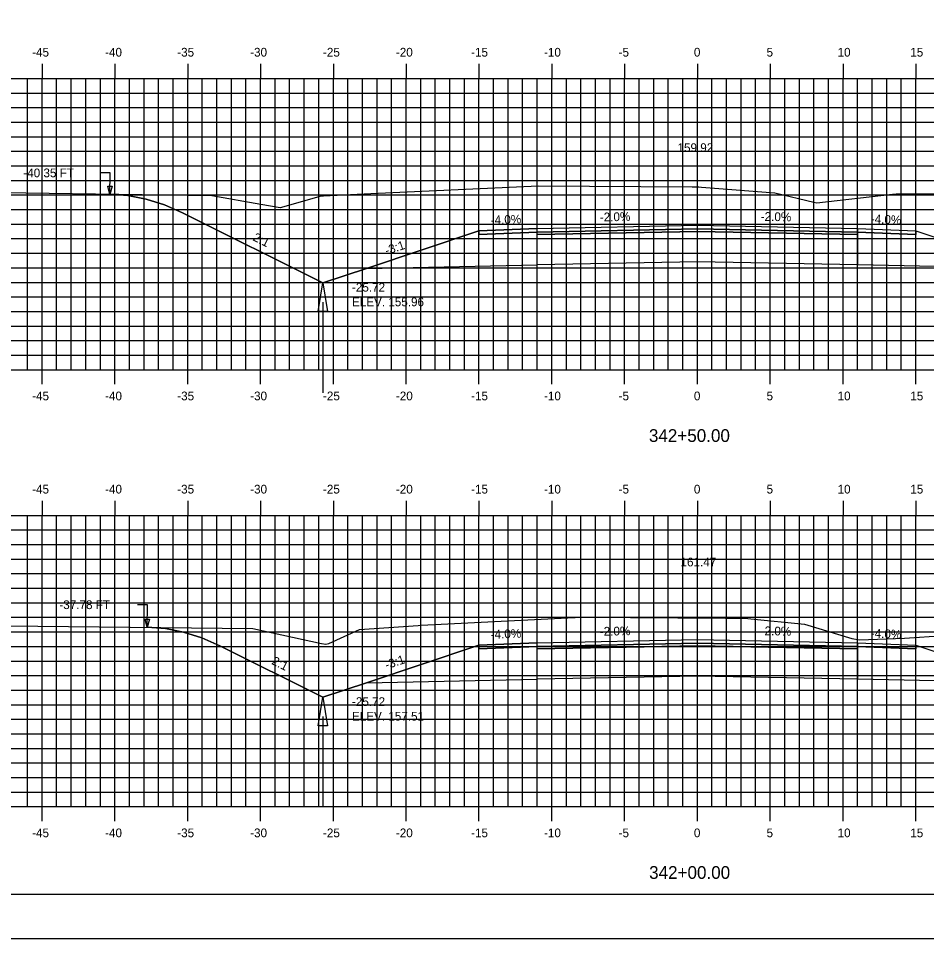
# Model space of a CAD drawing. Extents: x 1143198 to 1143368, y 608981 to 609091.
# Drawn here: x 1143234.7 to 1143297.1, y 608981.3 to 609044.5 of the extents above; entities that cross this region are included whole.
import ezdxf

# ---------------------------------------------------------------- set-up
doc = ezdxf.new("R2010")
doc.units = 0
for name, color, linetype in [('ANNOTATION', 7, 'Continuous'), ('BORDER', 7, 'Continuous'), ('D_Drainage_Ditch_Line', 7, 'Continuous'), ('D_Roadway_Centerline', 7, 'Continuous'), ('D_Roadway_Centerline_Text', 7, 'Continuous'), ('D_Roadway_Edge_Shoulder', 7, 'Continuous'), ('D_Roadway_Edge_TW', 7, 'Continuous'), ('D_Roadway_Pavement', 7, 'Continuous'), ('D_Roadway_SlopeLines', 7, 'Continuous'), ('D_Roadway_SubGrade', 7, 'Continuous'), ('D_Text_Standard', 7, 'Continuous'), ('H_V ANNOTATION', 7, 'Continuous'), ('MAJOR', 7, 'Continuous'), ('MINOR', 7, 'Continuous'), ('PLOT BOUNDARY', 7, 'Continuous'), ('S_Roadway_Centerline', 7, 'Continuous')]:
    doc.layers.add(name, color=color, linetype=linetype)

msp = doc.modelspace()

# ---------------------------------------------------------------- linework, layer by layer
for points in [[(1143240.971, 609032.398), (1143242.221, 609032.303), (1143243.471, 609032.057), (1143244.721, 609031.659), (1143245.971, 609031.11), (1143255.598, 609026.296), (1143258.598, 609027.296), (1143266.322, 609029.871), (1143266.323, 609029.871), (1143270.323, 609030.031), (1143281.323, 609030.251), (1143292.323, 609030.031), (1143296.323, 609029.871), (1143304.047, 609027.296), (1143307.047, 609026.296), (1143317.091, 609031.319), (1143318.341, 609031.867), (1143319.591, 609032.26), (1143320.841, 609032.5), (1143322.091, 609032.585)], [(1143243.539, 609002.652), (1143244.789, 609002.562), (1143246.039, 609002.32), (1143247.289, 609001.925), (1143248.539, 609001.376), (1143255.598, 608997.847), (1143258.598, 608998.847), (1143266.322, 609001.421), (1143266.323, 609001.421), (1143270.323, 609001.581), (1143281.323, 609001.801), (1143292.323, 609001.581), (1143296.323, 609001.421), (1143304.047, 608998.847), (1143307.047, 608997.847), (1143312.886, 609000.767), (1143314.136, 609001.313), (1143315.386, 609001.7), (1143316.636, 609001.93), (1143317.886, 609002.001)]]:
    msp.add_lwpolyline(points)
at = {"layer": 'BORDER'}
msp.add_lwpolyline([(1143206.323, 608984.335), (1143366.323, 608984.335), (1143366.323, 609089.335), (1143206.323, 609089.335)], close=True, dxfattribs=at)
at = {"layer": 'D_Drainage_Ditch_Line'}
for p, q in [((1143255.599, 609024.984), (1143255.598, 609018.741)), ((1143255.599, 608996.534), (1143255.598, 608990.291))]:
    msp.add_line(p, q, dxfattribs=at)
for points in [[(1143255.927, 609024.328), (1143255.27, 609024.328), (1143255.598, 609026.296)], [(1143255.927, 608995.878), (1143255.27, 608995.878), (1143255.598, 608997.847)]]:
    msp.add_lwpolyline(points, close=True, dxfattribs=at)
at = {"layer": 'D_Roadway_Edge_Shoulder'}
for points in [[(1143270.323, 609030.031), (1143266.323, 609029.871), (1143266.323, 609029.621), (1143270.323, 609029.781)], [(1143292.323, 609030.031), (1143296.323, 609029.871), (1143296.323, 609029.621), (1143292.323, 609029.781)], [(1143270.323, 609001.581), (1143266.323, 609001.421), (1143266.323, 609001.171), (1143270.323, 609001.331)], [(1143292.323, 609001.581), (1143296.323, 609001.421), (1143296.323, 609001.171), (1143292.323, 609001.331)]]:
    msp.add_lwpolyline(points, close=True, dxfattribs=at)
at = {"layer": 'D_Roadway_Edge_TW'}
for points in [[(1143270.323, 609029.781), (1143270.323, 609030.031), (1143281.323, 609030.251), (1143292.323, 609030.031), (1143292.323, 609029.781), (1143281.323, 609030.001)], [(1143270.323, 609001.331), (1143270.323, 609001.581), (1143281.323, 609001.801), (1143292.323, 609001.581), (1143292.323, 609001.331), (1143281.323, 609001.551)]]:
    msp.add_lwpolyline(points, close=True, dxfattribs=at)
at = {"layer": 'D_Roadway_Pavement'}
for points in [[(1143270.323, 609029.614), (1143270.323, 609029.781), (1143281.323, 609030.001), (1143292.323, 609029.781), (1143292.323, 609029.614), (1143281.323, 609029.834)], [(1143270.323, 609001.165), (1143270.323, 609001.331), (1143281.323, 609001.551), (1143292.323, 609001.331), (1143292.323, 609001.165), (1143281.323, 609001.385)]]:
    msp.add_lwpolyline(points, close=True, dxfattribs=at)
at = {"layer": 'D_Roadway_SlopeLines'}
for points in [[(1143255.598, 609026.296), (1143245.971, 609031.11), (1143244.721, 609031.659), (1143243.471, 609032.057), (1143242.221, 609032.303), (1143240.971, 609032.398)], [(1143258.598, 609027.296), (1143255.598, 609026.296)], [(1143255.598, 608997.847), (1143248.539, 609001.376), (1143247.289, 609001.925), (1143246.039, 609002.32), (1143244.789, 609002.562), (1143243.539, 609002.652)], [(1143258.598, 608998.847), (1143255.598, 608997.847)]]:
    msp.add_lwpolyline(points, dxfattribs=at)
at = {"layer": 'D_Roadway_SubGrade'}
for points in [[(1143270.323, 609029.614), (1143270.323, 609029.781), (1143266.323, 609029.621), (1143266.323, 609029.871), (1143266.322, 609029.871), (1143258.598, 609027.296), (1143270.323, 609027.531)], [(1143270.323, 609027.531), (1143270.323, 609029.614), (1143281.323, 609029.834), (1143292.323, 609029.614), (1143292.323, 609027.531), (1143281.323, 609027.751)], [(1143292.323, 609029.614), (1143292.323, 609029.781), (1143296.323, 609029.621), (1143296.323, 609029.871), (1143296.323, 609029.871), (1143304.047, 609027.296), (1143292.323, 609027.531)], [(1143270.323, 609001.165), (1143270.323, 609001.331), (1143266.323, 609001.171), (1143266.323, 609001.421), (1143266.322, 609001.421), (1143258.598, 608998.847), (1143270.323, 608999.081)], [(1143270.323, 608999.081), (1143270.323, 609001.165), (1143281.323, 609001.385), (1143292.323, 609001.165), (1143292.323, 608999.081), (1143281.323, 608999.301)], [(1143292.323, 609001.165), (1143292.323, 609001.331), (1143296.323, 609001.171), (1143296.323, 609001.421), (1143296.323, 609001.421), (1143304.047, 608998.847), (1143292.323, 608999.081)]]:
    msp.add_lwpolyline(points, close=True, dxfattribs=at)
at = {"layer": 'D_Text_Standard'}
for points in [[(1143240.971, 609032.36), (1143241.007, 609033.85), (1143240.327, 609033.85)], [(1143243.539, 609002.626), (1143243.558, 609004.201), (1143242.878, 609004.201)]]:
    msp.add_lwpolyline(points, dxfattribs=at)
for points in [[(1143240.971, 609032.36), (1143240.839, 609032.946), (1143241.13, 609032.939)], [(1143243.539, 609002.626), (1143243.401, 609003.21), (1143243.692, 609003.207)]]:
    msp.add_lwpolyline(points, close=True, dxfattribs=at)
at = {"layer": 'MAJOR'}
for p, q in [((1143236.323, 609041.337), (1143236.323, 609040.335)), ((1143241.323, 609041.337), (1143241.323, 609040.335)), ((1143246.323, 609041.337), (1143246.323, 609040.335)), ((1143251.323, 609041.337), (1143251.323, 609040.335)), ((1143256.323, 609041.337), (1143256.323, 609040.335)), ((1143261.323, 609041.337), (1143261.323, 609040.335)), ((1143266.323, 609041.337), (1143266.323, 609040.335)), ((1143271.323, 609041.337), (1143271.323, 609040.335)), ((1143276.323, 609041.337), (1143276.323, 609040.335)), ((1143281.323, 609041.337), (1143281.323, 609040.335)), ((1143286.323, 609041.337), (1143286.323, 609040.335)), ((1143291.323, 609041.337), (1143291.323, 609040.335)), ((1143296.323, 609041.337), (1143296.323, 609040.335)), ((1143211.323, 609040.335), (1143351.323, 609040.335)), ((1143211.323, 609040.335), (1143351.323, 609040.335)), ((1143236.323, 609020.335), (1143236.323, 609040.335)), ((1143241.323, 609020.335), (1143241.323, 609040.335)), ((1143246.323, 609020.335), (1143246.323, 609040.335)), ((1143251.323, 609020.335), (1143251.323, 609040.335)), ((1143256.323, 609020.335), (1143256.323, 609040.335)), ((1143261.323, 609020.335), (1143261.323, 609040.335)), ((1143266.323, 609020.335), (1143266.323, 609040.335)), ((1143271.323, 609020.335), (1143271.323, 609040.335)), ((1143276.323, 609020.335), (1143276.323, 609040.335)), ((1143281.323, 609020.335), (1143281.323, 609040.335)), ((1143286.323, 609020.335), (1143286.323, 609040.335)), ((1143291.323, 609020.335), (1143291.323, 609040.335)), ((1143296.323, 609020.335), (1143296.323, 609040.335)), ((1143211.323, 609035.335), (1143351.323, 609035.335)), ((1143211.323, 609030.335), (1143351.323, 609030.335)), ((1143211.323, 609025.335), (1143351.323, 609025.335)), ((1143211.323, 609020.335), (1143351.323, 609020.335)), ((1143211.323, 609020.335), (1143351.323, 609020.335)), ((1143236.323, 609019.333), (1143236.323, 609020.335)), ((1143241.323, 609019.333), (1143241.323, 609020.335)), ((1143246.323, 609019.333), (1143246.323, 609020.335)), ((1143251.323, 609019.333), (1143251.323, 609020.335)), ((1143256.323, 609019.333), (1143256.323, 609020.335)), ((1143261.323, 609019.333), (1143261.323, 609020.335)), ((1143266.323, 609019.333), (1143266.323, 609020.335)), ((1143271.323, 609019.333), (1143271.323, 609020.335)), ((1143276.323, 609019.333), (1143276.323, 609020.335)), ((1143281.323, 609019.333), (1143281.323, 609020.335)), ((1143286.323, 609019.333), (1143286.323, 609020.335)), ((1143291.323, 609019.333), (1143291.323, 609020.335)), ((1143296.323, 609019.333), (1143296.323, 609020.335)), ((1143236.323, 609011.337), (1143236.323, 609010.335)), ((1143241.323, 609011.337), (1143241.323, 609010.335)), ((1143246.323, 609011.337), (1143246.323, 609010.335)), ((1143251.323, 609011.337), (1143251.323, 609010.335)), ((1143256.323, 609011.337), (1143256.323, 609010.335)), ((1143261.323, 609011.337), (1143261.323, 609010.335)), ((1143266.323, 609011.337), (1143266.323, 609010.335)), ((1143271.323, 609011.337), (1143271.323, 609010.335)), ((1143276.323, 609011.337), (1143276.323, 609010.335)), ((1143281.323, 609011.337), (1143281.323, 609010.335)), ((1143286.323, 609011.337), (1143286.323, 609010.335)), ((1143291.323, 609011.337), (1143291.323, 609010.335)), ((1143296.323, 609011.337), (1143296.323, 609010.335)), ((1143211.323, 609010.335), (1143351.323, 609010.335)), ((1143211.323, 609010.335), (1143351.323, 609010.335)), ((1143236.323, 608990.335), (1143236.323, 609010.335)), ((1143241.323, 608990.335), (1143241.323, 609010.335)), ((1143246.323, 608990.335), (1143246.323, 609010.335)), ((1143251.323, 608990.335), (1143251.323, 609010.335)), ((1143256.323, 608990.335), (1143256.323, 609010.335)), ((1143261.323, 608990.335), (1143261.323, 609010.335)), ((1143266.323, 608990.335), (1143266.323, 609010.335)), ((1143271.323, 608990.335), (1143271.323, 609010.335)), ((1143276.323, 608990.335), (1143276.323, 609010.335)), ((1143281.323, 608990.335), (1143281.323, 609010.335)), ((1143286.323, 608990.335), (1143286.323, 609010.335)), ((1143291.323, 608990.335), (1143291.323, 609010.335)), ((1143296.323, 608990.335), (1143296.323, 609010.335)), ((1143211.323, 609005.335), (1143351.323, 609005.335)), ((1143211.323, 609000.335), (1143351.323, 609000.335)), ((1143211.323, 608995.335), (1143351.323, 608995.335)), ((1143211.323, 608990.335), (1143351.323, 608990.335)), ((1143211.323, 608990.335), (1143351.323, 608990.335)), ((1143236.323, 608989.333), (1143236.323, 608990.335)), ((1143241.323, 608989.333), (1143241.323, 608990.335)), ((1143246.323, 608989.333), (1143246.323, 608990.335)), ((1143251.323, 608989.333), (1143251.323, 608990.335)), ((1143256.323, 608989.333), (1143256.323, 608990.335)), ((1143261.323, 608989.333), (1143261.323, 608990.335)), ((1143266.323, 608989.333), (1143266.323, 608990.335)), ((1143271.323, 608989.333), (1143271.323, 608990.335)), ((1143276.323, 608989.333), (1143276.323, 608990.335)), ((1143281.323, 608989.333), (1143281.323, 608990.335)), ((1143286.323, 608989.333), (1143286.323, 608990.335)), ((1143291.323, 608989.333), (1143291.323, 608990.335)), ((1143296.323, 608989.333), (1143296.323, 608990.335))]:
    msp.add_line(p, q, dxfattribs=at)
at = {"layer": 'MINOR'}
for p, q in [((1143235.323, 609020.335), (1143235.323, 609040.335)), ((1143237.323, 609020.335), (1143237.323, 609040.335)), ((1143238.323, 609020.335), (1143238.323, 609040.335)), ((1143239.323, 609020.335), (1143239.323, 609040.335)), ((1143240.323, 609020.335), (1143240.323, 609040.335)), ((1143242.323, 609020.335), (1143242.323, 609040.335)), ((1143243.323, 609020.335), (1143243.323, 609040.335)), ((1143244.323, 609020.335), (1143244.323, 609040.335)), ((1143245.323, 609020.335), (1143245.323, 609040.335)), ((1143247.323, 609020.335), (1143247.323, 609040.335)), ((1143248.323, 609020.335), (1143248.323, 609040.335)), ((1143249.323, 609020.335), (1143249.323, 609040.335)), ((1143250.323, 609020.335), (1143250.323, 609040.335)), ((1143252.323, 609020.335), (1143252.323, 609040.335)), ((1143253.323, 609020.335), (1143253.323, 609040.335)), ((1143254.323, 609020.335), (1143254.323, 609040.335)), ((1143255.323, 609020.335), (1143255.323, 609040.335)), ((1143257.323, 609020.335), (1143257.323, 609040.335)), ((1143258.323, 609020.335), (1143258.323, 609040.335)), ((1143259.323, 609020.335), (1143259.323, 609040.335)), ((1143260.323, 609020.335), (1143260.323, 609040.335)), ((1143262.323, 609020.335), (1143262.323, 609040.335)), ((1143263.323, 609020.335), (1143263.323, 609040.335)), ((1143264.323, 609020.335), (1143264.323, 609040.335)), ((1143265.323, 609020.335), (1143265.323, 609040.335)), ((1143267.323, 609020.335), (1143267.323, 609040.335)), ((1143268.323, 609020.335), (1143268.323, 609040.335)), ((1143269.323, 609020.335), (1143269.323, 609040.335)), ((1143270.323, 609020.335), (1143270.323, 609040.335)), ((1143272.323, 609020.335), (1143272.323, 609040.335)), ((1143273.323, 609020.335), (1143273.323, 609040.335)), ((1143274.323, 609020.335), (1143274.323, 609040.335)), ((1143275.323, 609020.335), (1143275.323, 609040.335)), ((1143277.323, 609020.335), (1143277.323, 609040.335)), ((1143278.323, 609020.335), (1143278.323, 609040.335)), ((1143279.323, 609020.335), (1143279.323, 609040.335)), ((1143280.323, 609020.335), (1143280.323, 609040.335)), ((1143282.323, 609020.335), (1143282.323, 609040.335)), ((1143283.323, 609020.335), (1143283.323, 609040.335)), ((1143284.323, 609020.335), (1143284.323, 609040.335)), ((1143285.323, 609020.335), (1143285.323, 609040.335)), ((1143287.323, 609020.335), (1143287.323, 609040.335)), ((1143288.323, 609020.335), (1143288.323, 609040.335)), ((1143289.323, 609020.335), (1143289.323, 609040.335)), ((1143290.323, 609020.335), (1143290.323, 609040.335)), ((1143292.323, 609020.335), (1143292.323, 609040.335)), ((1143293.323, 609020.335), (1143293.323, 609040.335)), ((1143294.323, 609020.335), (1143294.323, 609040.335)), ((1143295.323, 609020.335), (1143295.323, 609040.335)), ((1143211.323, 609039.335), (1143351.323, 609039.335)), ((1143211.323, 609038.335), (1143351.323, 609038.335)), ((1143211.323, 609037.335), (1143351.323, 609037.335)), ((1143211.323, 609036.335), (1143351.323, 609036.335)), ((1143211.323, 609034.335), (1143351.323, 609034.335)), ((1143211.323, 609033.335), (1143351.323, 609033.335)), ((1143211.323, 609032.335), (1143351.323, 609032.335)), ((1143211.323, 609031.335), (1143351.323, 609031.335)), ((1143211.323, 609029.335), (1143351.323, 609029.335)), ((1143211.323, 609028.335), (1143351.323, 609028.335)), ((1143211.323, 609027.335), (1143351.323, 609027.335)), ((1143211.323, 609026.335), (1143351.323, 609026.335)), ((1143211.323, 609024.335), (1143351.323, 609024.335)), ((1143211.323, 609023.335), (1143351.323, 609023.335)), ((1143211.323, 609022.335), (1143351.323, 609022.335)), ((1143211.323, 609021.335), (1143351.323, 609021.335)), ((1143235.323, 608990.335), (1143235.323, 609010.335)), ((1143237.323, 608990.335), (1143237.323, 609010.335)), ((1143238.323, 608990.335), (1143238.323, 609010.335)), ((1143239.323, 608990.335), (1143239.323, 609010.335)), ((1143240.323, 608990.335), (1143240.323, 609010.335)), ((1143242.323, 608990.335), (1143242.323, 609010.335)), ((1143243.323, 608990.335), (1143243.323, 609010.335)), ((1143244.323, 608990.335), (1143244.323, 609010.335)), ((1143245.323, 608990.335), (1143245.323, 609010.335)), ((1143247.323, 608990.335), (1143247.323, 609010.335)), ((1143248.323, 608990.335), (1143248.323, 609010.335)), ((1143249.323, 608990.335), (1143249.323, 609010.335)), ((1143250.323, 608990.335), (1143250.323, 609010.335)), ((1143252.323, 608990.335), (1143252.323, 609010.335)), ((1143253.323, 608990.335), (1143253.323, 609010.335)), ((1143254.323, 608990.335), (1143254.323, 609010.335)), ((1143255.323, 608990.335), (1143255.323, 609010.335)), ((1143257.323, 608990.335), (1143257.323, 609010.335)), ((1143258.323, 608990.335), (1143258.323, 609010.335)), ((1143259.323, 608990.335), (1143259.323, 609010.335)), ((1143260.323, 608990.335), (1143260.323, 609010.335)), ((1143262.323, 608990.335), (1143262.323, 609010.335)), ((1143263.323, 608990.335), (1143263.323, 609010.335)), ((1143264.323, 608990.335), (1143264.323, 609010.335)), ((1143265.323, 608990.335), (1143265.323, 609010.335)), ((1143267.323, 608990.335), (1143267.323, 609010.335)), ((1143268.323, 608990.335), (1143268.323, 609010.335)), ((1143269.323, 608990.335), (1143269.323, 609010.335)), ((1143270.323, 608990.335), (1143270.323, 609010.335)), ((1143272.323, 608990.335), (1143272.323, 609010.335)), ((1143273.323, 608990.335), (1143273.323, 609010.335)), ((1143274.323, 608990.335), (1143274.323, 609010.335)), ((1143275.323, 608990.335), (1143275.323, 609010.335)), ((1143277.323, 608990.335), (1143277.323, 609010.335)), ((1143278.323, 608990.335), (1143278.323, 609010.335)), ((1143279.323, 608990.335), (1143279.323, 609010.335)), ((1143280.323, 608990.335), (1143280.323, 609010.335)), ((1143282.323, 608990.335), (1143282.323, 609010.335)), ((1143283.323, 608990.335), (1143283.323, 609010.335)), ((1143284.323, 608990.335), (1143284.323, 609010.335)), ((1143285.323, 608990.335), (1143285.323, 609010.335)), ((1143287.323, 608990.335), (1143287.323, 609010.335)), ((1143288.323, 608990.335), (1143288.323, 609010.335)), ((1143289.323, 608990.335), (1143289.323, 609010.335)), ((1143290.323, 608990.335), (1143290.323, 609010.335)), ((1143292.323, 608990.335), (1143292.323, 609010.335)), ((1143293.323, 608990.335), (1143293.323, 609010.335)), ((1143294.323, 608990.335), (1143294.323, 609010.335)), ((1143295.323, 608990.335), (1143295.323, 609010.335)), ((1143211.323, 609009.335), (1143351.323, 609009.335)), ((1143211.323, 609008.335), (1143351.323, 609008.335)), ((1143211.323, 609007.335), (1143351.323, 609007.335)), ((1143211.323, 609006.335), (1143351.323, 609006.335)), ((1143211.323, 609004.335), (1143351.323, 609004.335)), ((1143211.323, 609003.335), (1143351.323, 609003.335)), ((1143211.323, 609002.335), (1143351.323, 609002.335)), ((1143211.323, 609001.335), (1143351.323, 609001.335)), ((1143211.323, 608999.335), (1143351.323, 608999.335)), ((1143211.323, 608998.335), (1143351.323, 608998.335)), ((1143211.323, 608997.335), (1143351.323, 608997.335)), ((1143211.323, 608996.335), (1143351.323, 608996.335)), ((1143211.323, 608994.335), (1143351.323, 608994.335)), ((1143211.323, 608993.335), (1143351.323, 608993.335)), ((1143211.323, 608992.335), (1143351.323, 608992.335)), ((1143211.323, 608991.335), (1143351.323, 608991.335))]:
    msp.add_line(p, q, dxfattribs=at)
at = {"layer": 'PLOT BOUNDARY'}
msp.add_lwpolyline([(1143198.23, 608981.276), (1143368.23, 608981.276), (1143368.23, 609091.276), (1143198.23, 609091.276)], close=True, dxfattribs=at)
at = {"layer": 'S_Roadway_Centerline'}
for points in [[(1143211.323, 609032.36), (1143212.821, 609032.367), (1143227.649, 609032.583), (1143228.657, 609032.591), (1143228.8, 609032.583), (1143247.983, 609032.292), (1143251.333, 609031.712), (1143252.666, 609031.463), (1143252.702, 609031.479), (1143255.498, 609032.264), (1143255.639, 609032.274), (1143258.901, 609032.437), (1143269.916, 609032.935), (1143270.397, 609032.96), (1143280.959, 609032.894), (1143281.429, 609032.891), (1143281.615, 609032.872), (1143286.632, 609032.483), (1143289.312, 609031.85), (1143289.514, 609031.79), (1143294.73, 609032.394), (1143294.969, 609032.411), (1143322.054, 609032.585)], [(1143211.323, 609002.363), (1143225.121, 609002.802), (1143229.877, 609002.851), (1143231.792, 609002.771), (1143250.788, 609002.578), (1143255.519, 609001.533), (1143255.814, 609001.5), (1143256.006, 609001.549), (1143258.121, 609002.489), (1143262.156, 609002.773), (1143262.353, 609002.794), (1143272.425, 609003.307), (1143273.453, 609003.347), (1143283.253, 609003.281), (1143284.582, 609003.27), (1143284.986, 609003.233), (1143288.677, 609002.857), (1143291.938, 609001.891), (1143292.456, 609001.78), (1143295.537, 609001.911), (1143298.268, 609002.095)]]:
    msp.add_lwpolyline(points, dxfattribs=at)

# ---------------------------------------------------------------- texts
at = {"layer": 'ANNOTATION'}
for s, rotation, p in [('-4.0%', 2.29061, (1143267.139, 609030.304)), ('-2.0%', 1.14576, (1143274.626, 609030.517)), ('-2.0%', 358.85424, (1143285.666, 609030.564)), ('-4.0%', 357.70939, (1143293.219, 609030.396)), ('2:1', 333.43495, (1143250.752, 609029.238)), ('-3:1', 18.43482, (1143259.977, 609028.21)), ('-4.0%', 2.29061, (1143267.139, 609001.855)), ('-2.0%', 1.14576, (1143274.626, 609002.068)), ('-2.0%', 358.85424, (1143285.666, 609002.115)), ('-4.0%', 357.70939, (1143293.219, 609001.946)), ('2:1', 333.43495, (1143252.036, 609000.146)), ('-3:1', 18.43482, (1143259.977, 608999.76))]:
    msp.add_text(s, height=0.6, rotation=rotation, dxfattribs=at).set_placement(p)
at = {"layer": 'D_Roadway_Centerline'}
for s, p in [('C', (1143281.318, 609030.251)), ('L', (1143281.323, 609030.244)), ('C', (1143281.318, 609001.801)), ('L', (1143281.323, 609001.794))]:
    msp.add_text(s, height=0.0146, dxfattribs=at).set_placement(p)
at = {"layer": 'D_Roadway_Centerline_Text'}
for s, p in [('159.92', (1143279.956, 609035.283)), ('161.47', (1143280.162, 609006.833))]:
    msp.add_text(s, height=0.6, dxfattribs=at).set_placement(p)
at = {"layer": 'D_Text_Standard'}
for s, p in [('-40.35 FT', (1143235.033, 609033.55)), ('-25.72', (1143257.599, 609025.696)), ('ELEV. 155.96', (1143257.599, 609024.694)), ('-37.78 FT', (1143237.509, 609003.901)), ('-25.72', (1143257.599, 608997.247)), ('ELEV. 157.51', (1143257.599, 608996.245))]:
    msp.add_text(s, height=0.6, dxfattribs=at).set_placement(p)
at = {"layer": 'H_V ANNOTATION'}
for s, height, p in [('-45', 0.6, (1143235.641, 609041.835)), ('-40', 0.6, (1143240.649, 609041.835)), ('-35', 0.6, (1143245.603, 609041.835)), ('-30', 0.6, (1143250.611, 609041.835)), ('-25', 0.6, (1143255.609, 609041.835)), ('-20', 0.6, (1143260.617, 609041.835)), ('-15', 0.6, (1143265.78, 609041.835)), ('-10', 0.6, (1143270.788, 609041.835)), ('-5', 0.6, (1143275.914, 609041.835)), ('0', 0.6, (1143281.082, 609041.835)), ('5', 0.6, (1143286.074, 609041.835)), ('10', 0.6, (1143290.948, 609041.835)), ('15', 0.6, (1143295.94, 609041.835)), ('-45', 0.6, (1143235.641, 609018.235)), ('-40', 0.6, (1143240.649, 609018.235)), ('-35', 0.6, (1143245.603, 609018.235)), ('-30', 0.6, (1143250.611, 609018.235)), ('-25', 0.6, (1143255.609, 609018.235)), ('-20', 0.6, (1143260.617, 609018.235)), ('-15', 0.6, (1143265.78, 609018.235)), ('-10', 0.6, (1143270.788, 609018.235)), ('-5', 0.6, (1143275.914, 609018.235)), ('0', 0.6, (1143281.082, 609018.235)), ('5', 0.6, (1143286.074, 609018.235)), ('10', 0.6, (1143290.948, 609018.235)), ('15', 0.6, (1143295.94, 609018.235)), ('342+50.00', 0.875, (1143277.991, 609015.378)), ('-45', 0.6, (1143235.641, 609011.835)), ('-40', 0.6, (1143240.649, 609011.835)), ('-35', 0.6, (1143245.603, 609011.835)), ('-30', 0.6, (1143250.611, 609011.835)), ('-25', 0.6, (1143255.609, 609011.835)), ('-20', 0.6, (1143260.617, 609011.835)), ('-15', 0.6, (1143265.78, 609011.835)), ('-10', 0.6, (1143270.788, 609011.835)), ('-5', 0.6, (1143275.914, 609011.835)), ('0', 0.6, (1143281.082, 609011.835)), ('5', 0.6, (1143286.074, 609011.835)), ('10', 0.6, (1143290.948, 609011.835)), ('15', 0.6, (1143295.94, 609011.835)), ('-45', 0.6, (1143235.641, 608988.235)), ('-40', 0.6, (1143240.649, 608988.235)), ('-35', 0.6, (1143245.603, 608988.235)), ('-30', 0.6, (1143250.611, 608988.235)), ('-25', 0.6, (1143255.609, 608988.235)), ('-20', 0.6, (1143260.617, 608988.235)), ('-15', 0.6, (1143265.78, 608988.235)), ('-10', 0.6, (1143270.788, 608988.235)), ('-5', 0.6, (1143275.914, 608988.235)), ('0', 0.6, (1143281.082, 608988.235)), ('5', 0.6, (1143286.074, 608988.235)), ('10', 0.6, (1143290.948, 608988.235)), ('15', 0.6, (1143295.94, 608988.235)), ('342+00.00', 0.875, (1143278.007, 608985.378))]:
    msp.add_text(s, height=height, dxfattribs=at).set_placement(p)
at = {"layer": 'S_Roadway_Centerline'}
for s, p in [('L', (1143270.389, 609032.952)), ('C', (1143270.392, 609032.96)), ('L', (1143273.444, 609003.34)), ('C', (1143273.447, 609003.347))]:
    msp.add_text(s, height=0.0146, dxfattribs=at).set_placement(p)

doc.saveas('drawing.dxf')
